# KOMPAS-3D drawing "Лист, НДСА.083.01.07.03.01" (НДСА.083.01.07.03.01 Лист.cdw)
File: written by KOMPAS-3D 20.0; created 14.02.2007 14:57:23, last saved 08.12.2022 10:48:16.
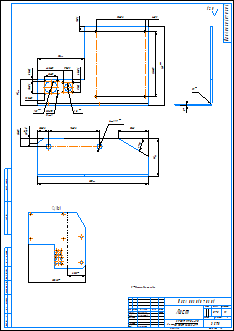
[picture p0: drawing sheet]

Sheet 1: A2, portrait

Document properties: Автор: Шубников; Организация: ЭСТО-Вакуум; Масса: 0.745208; Параметр неуказанной шероховатости: 12,5; PLM_CDWXDTO: <item xmlns="http://appius.ru/pdm" xmlns:xs="http://www.w3.org/2001/XMLSchema" xmlns:xsi="http://www.w3.org/2001/XMLSchema-instance" xsi:type="item">  <element xmlns:d2p1="http://v8.1c.ru/8.1/data/enterprise/current-config" xsi:type="d2p1:CatalogRef.aps_Элемен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; Полное имя файла: C:\Users\cherbakova\Desktop\Виноград\Новая папка (3)\НДСА.083.01.07.03.01 Лист.cdw

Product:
- Part/product: Лист  | designation НДСА.083.01.07.03.01
    Материал: Лист$d3 ГОСТ 19904-90;10 ГОСТ 16523-97$ (density 7856 kg/m3)
    Масса: 0.745208

Title block, sheet 1: Наименование: Лист; designation: НДСА.083.01.07.03.01; Материал: Лист 3 ГОСТ 19904-90 10 ГОСТ 16523-97; Масса: 0,75; scale: 1:1; Количество листов документа: 1; organisation: ЭСТО; Форматы листов документа: A2; stored path: E:\WorkPDM\Шубников А.В\1e050b01-88cf-474d-9aa8-68330efd0d1d\УКРД.787.01.12.10.01 Лист.cdw; Разработал: Щербакова; Проверил: Горностаев; Утвердил: Белецкий; Разработал, date: 08.12.2022
Table, sheet 1:
  0;Material:VDE12371B5FDD453AAD3A0896F0FE5778;Sortament:VBE6DDF6ADAD111D69930000021274E8E^SortamentEx:V409D97DD20334DB28E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

Views: Проекционный вид 3, Проекционный вид 4, Проекционный вид 5, Вид 6, Слева, Развертка
Referenced files in C:\Users\cherbakova\Desktop\Виноград\Новая папка (3)\: НДСА.083.01.07.03.01 Лист.m3d
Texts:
  НДСА.083.01.07.03.01 Лист
Dimensions and other numbers on the sheet: 143; 48; 85; 6±0,1; 9±0,1; 118±0,2; 88±0,2; 23±0,1; 14; 3,5±0,1; 13,5±0,1; 46,5±0,1; 17±0,1; 6,5±0,1; -7H; 3; 8 отв.; 200; 68; 10; 55±1; 20±0,2; 92±0,2; 15±0,2; 2отв.; 1; 206,22; 65,61; 12,5; 1:1; 0,75; 08.12.2022

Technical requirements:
  1. * Размеры для справок.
